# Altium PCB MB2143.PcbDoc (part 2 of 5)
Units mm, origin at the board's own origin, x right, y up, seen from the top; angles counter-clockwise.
Board outline 70 x 70 mm, 4 copper layers (Top Layer, Signal Layer 1, Signal Layer 2, Bottom Layer), stack 1.56 mm thick; 272 components, 188 nets, 1083 pads, 1158 vias.
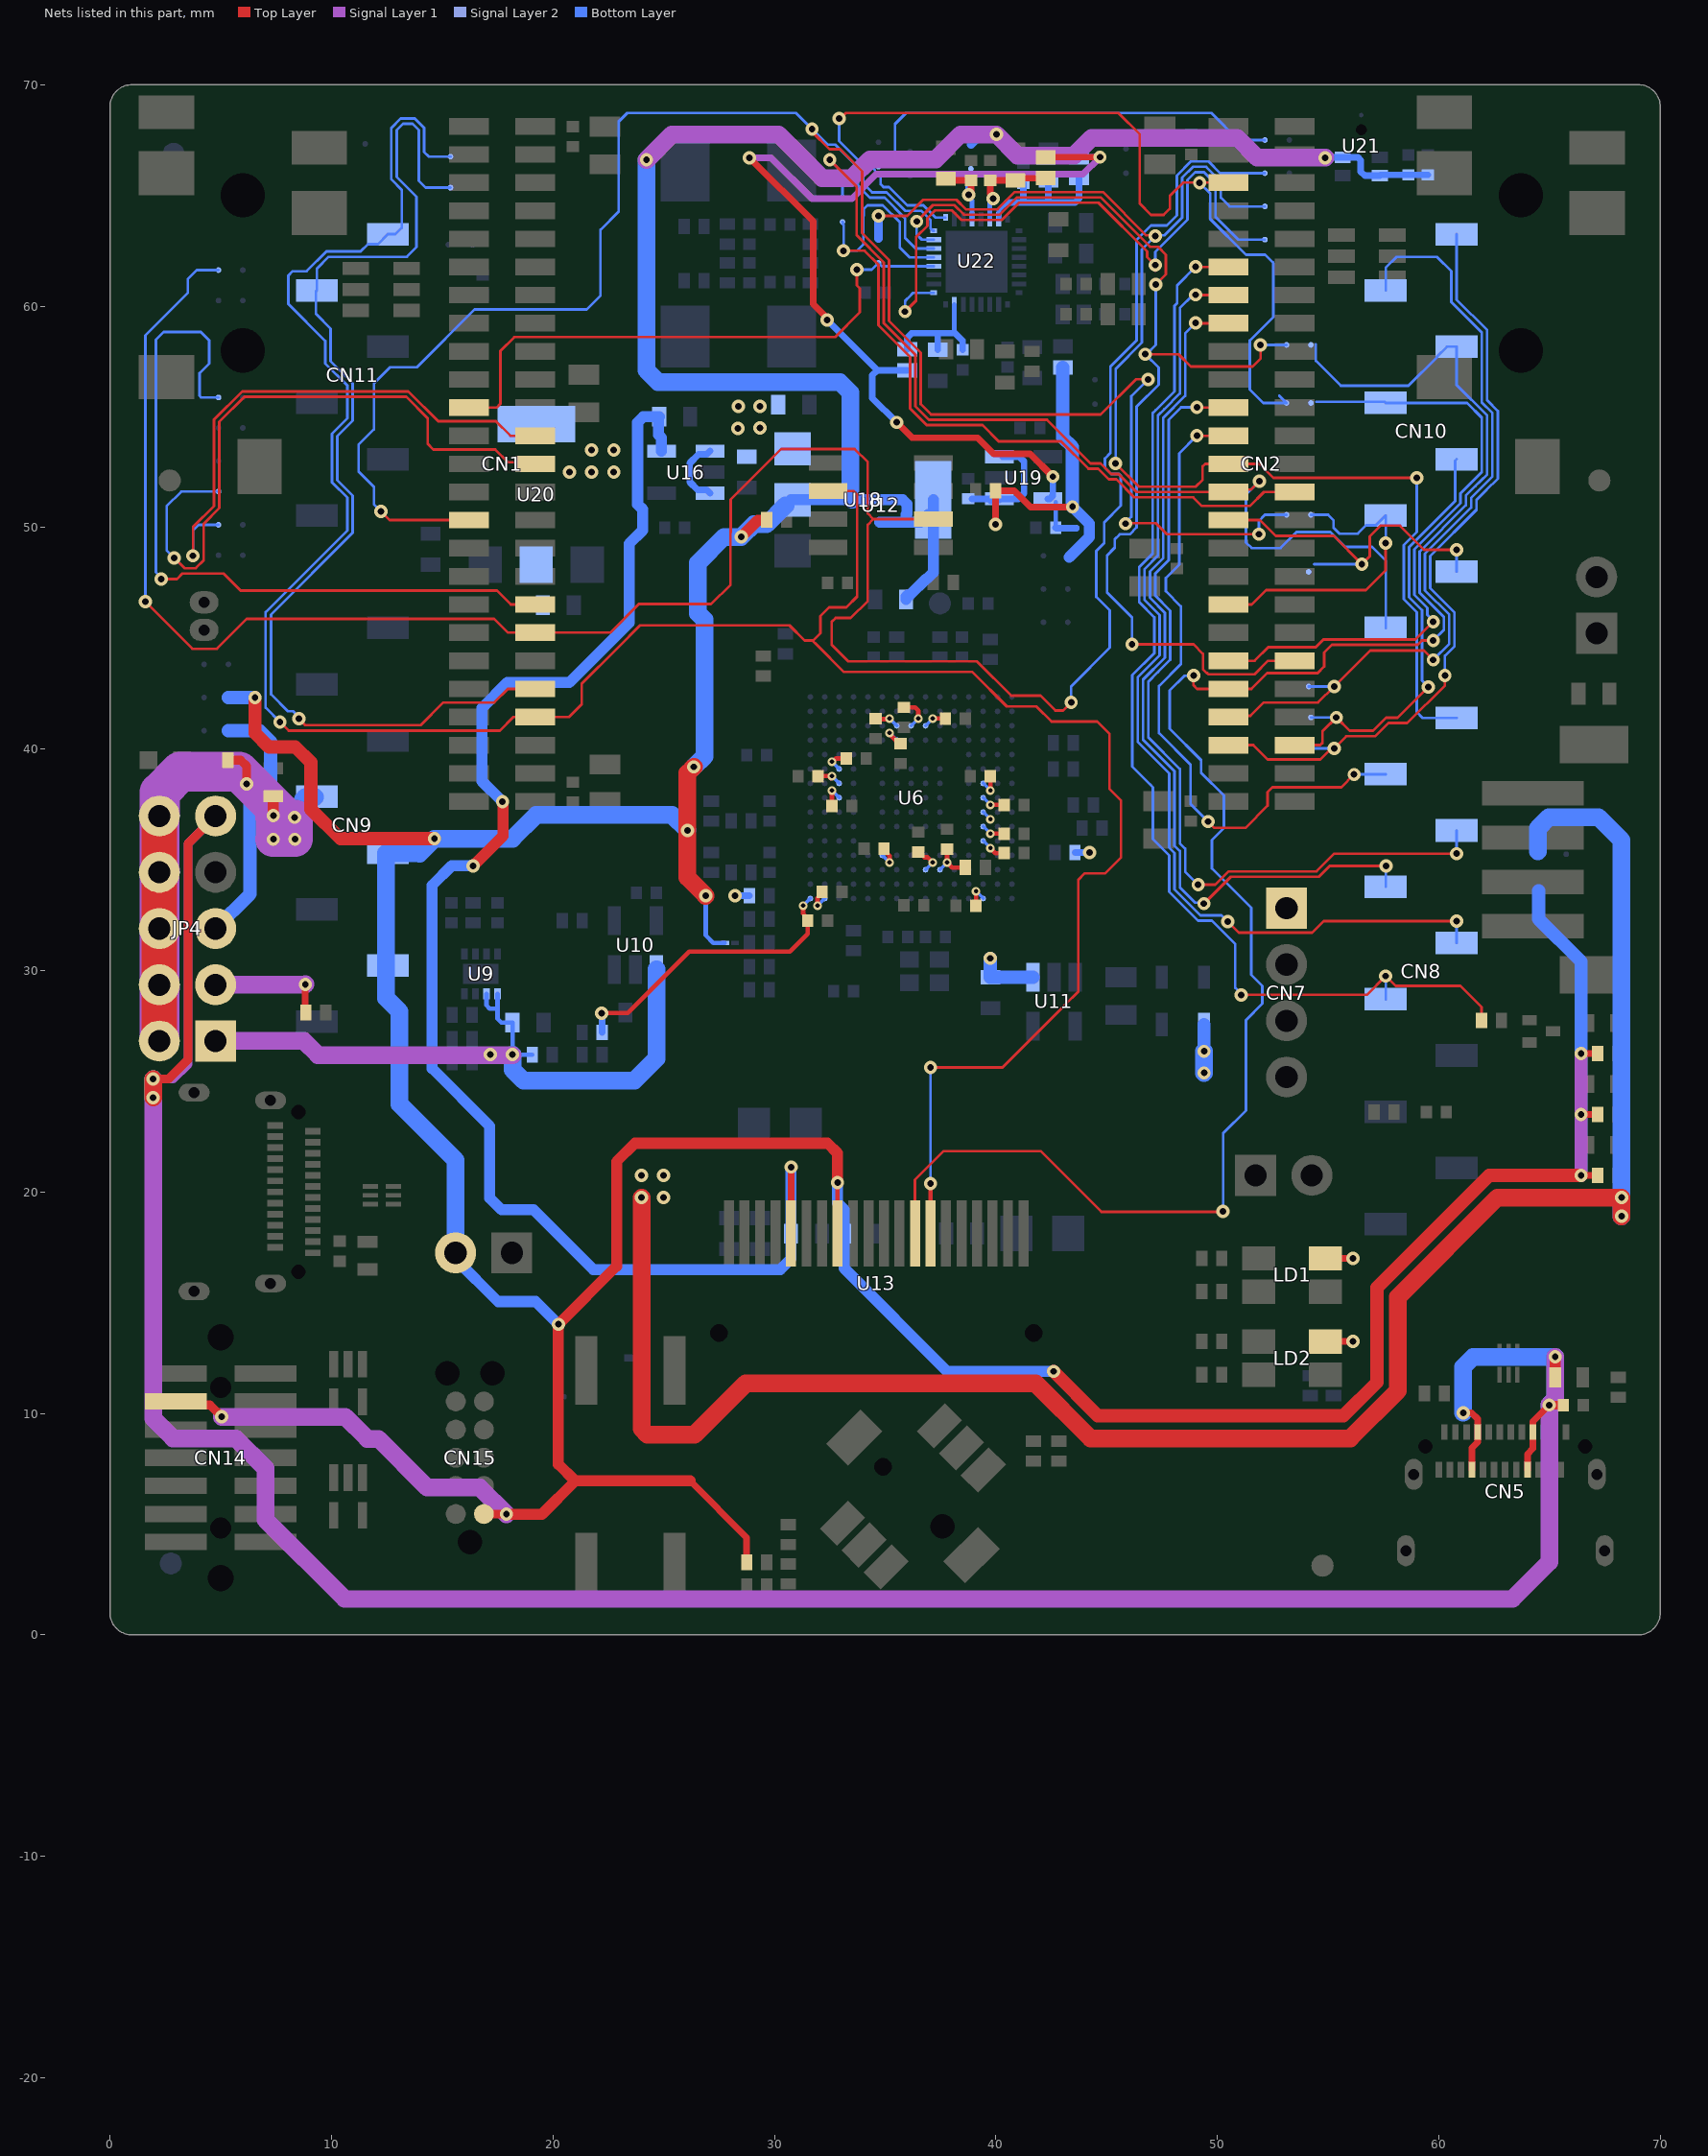
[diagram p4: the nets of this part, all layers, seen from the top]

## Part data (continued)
JP2 JP3: library part MCD-00045, "Header, 2x1, 2,54mm, VR, TH, Height 5.84mm/2.54mm", Manufacturer=SAMTEC, Manufacturer_Part_Number=TSW-102-07-x-S
JP4: library part MCD-01203, "Header, 5x2, 2.54mm, VR, TH, T=5.84mm/2.54mm", Manufacturer=SAMTEC, Manufacturer_Part_Number=TSW-105-07-G-D
L1 L3 L5 L6 L7 L8: library part MCD-02381, "Ferrite bead, 10R @100MHz, 5R, 0.75A, 0.07R, 0402, T=0.22mm", Manufacturer=MURATA, Manufacturer_Part_Number=BLM02AX100SN1D, Package=0402
LD1 LD2: library part MCD-02631, "LED Bicolor, Green/Red, 2V, 20mA,  4-PLCC", Manufacturer="WURTH ELEKTRONIK", Manufacturer_Part_Number=150141SV73110, Package=4-PLCC
LD3: library part MCD-00584, "LED Blue, 0603 SMD, 3.3 V Forward Voltage", Manufacturer=VISHAY, Manufacturer_Part_Number=VLMB1300-GS08, Package="LED 0603"
LD4: library part MCD-02901, "LED, Green, 2V, 20mA, 0603", Manufacturer=EVERLIGHT, Manufacturer_Part_Number=19-217/G7C-AN1P2/6T, Package=0603
LD5: library part MCD-00587, "LED Red, 0603 SMD, 2V Forward Voltage", Manufacturer=VISHAY, Manufacturer_Part_Number=VLMS1300-GS08, Package="LED 0603"
LD6: library part MCD-00589, "LED Green, 0603 SMD, Fw Voltage = 2.8V - 3.6V", Manufacturer=VISHAY, Manufacturer_Part_Number=VLMTG1300-GS08, Package="LED 0603"
LNK1: library part MCD-02777, "Track link on PCB 200um width for layout routing. No component assembly and no component in BOM", Manufacturer=STM, Package=LNK200
Q1: library part MCD-00280, "Buffer transistor", Manufacturer=ROHM
R1: library part MCD-00333, "Resistor, 5K1, 0402, +/-1%, 1/16W", Alternate_Manufacturer=N/A, Manufacturer=YAGEO, Manufacturer_Part_Number=RC0402FR-075K1L, Package=0402
R2: library part MCD-00409, "Resistor, 1K8, 0402, +/-1%, 1/16W", Alternate_Manufacturer=N/A, Manufacturer=YAGEO, Manufacturer_Part_Number=RC0402FR-071K8L, Package=0402
R3: library part MCD-00527, "Resistor, 820R, 0402, +/-1%, 1/16W", Alternate_Manufacturer=N/A, Manufacturer=YAGEO, Manufacturer_Part_Number=RC0402FR-07820RL, Package=0402
R4: library part MCD-00064, "Resistor, 510R, 0402, +/-1%, 1/16W", Alternate_Manufacturer=N/A, Manufacturer=YAGEO, Manufacturer_Part_Number=RC0402FR-07510RL, Package=0402
R5: library part MCD-00220, "Resistor,10K,0603,1%,1/10W", Manufacturer=YAGEO, Manufacturer_Part_Number=RC0603FR-0710KL, Package=R0603
R6 R7 R11 R15 R22: library part MCD-00333, "Resistor, 5K1, 0402, +/-1%, 1/16W", Manufacturer=YAGEO, Manufacturer_Part_Number=RC0402FR-075K1L, Package=0402
R8 R9: library part MCD-00065, "Resistor,4K7,0402,1%,1/16W", Alternate_Manufacturer=YAGEO, Alternate_Manufacturer_Part_Number=RT0402FRE074K7L, Manufacturer_Part_Number=RC0402FR-074K7L, Package=R0402
R10 R55: library part MCD-00053, "Resistor,10K,0402,1%,1/16W", Manufacturer=YAGEO, Manufacturer_Part_Number=RC0402FR-0710KL, Package=R0402
R12 R47: library part MCD-00067, "Resistor, 100R, 0402, +/- 1%, 1/16W", Manufacturer=YAGEO, Manufacturer_Part_Number=RC0402FR-07100RL, Package=0402
R13 R14 R34 R39 R40 R59: library part MCD-00059, "Resistor, 100K, 0402, +/-1%, 1/16W", Manufacturer=YAGEO, Manufacturer_Part_Number=RC0402FR-07100KL, Package=0402
R16 R18 R19 R21 R57: library part MCD-00455, "Resistor, 33R, 0402, +/-1%, 1/16W", Manufacturer=YAGEO, Manufacturer_Part_Number=RC0402FR-0733RL, Package=0402
R17 R20 R24 R58: library part MCD-00052, "Resistor, 0R, 0402, +/-5%, 1/16W", Manufacturer=YAGEO, Manufacturer_Part_Number=RC0402JR-070RL, Package=0402
R23 R26 R27 R28 R64: library part MCD-00053, "Resistor, 10K, 0402, +/-1%, 1/16W", Manufacturer=YAGEO, Manufacturer_Part_Number=RC0402FR-0710KL, Package=0402
R25 R29: library part MCD-00185, "Resistor, 3K, 0402, +/-1%, 1/16W", Manufacturer=YAGEO, Manufacturer_Part_Number=RC0402FR-073KL, Package=0402
R30 R33: library part MCD-02455, "Resistor, 3K9, 0402, +/-1%, 1/16W, +/-100ppm/°C", Manufacturer=YAGEO, Manufacturer_Part_Number=RC0402FR-073K9L, Package=0402
R31: library part MCD-00409, "Resistor, 1K8, 0402, +/-1%, 1/16W", Manufacturer=YAGEO, Manufacturer_Part_Number=RC0402FR-071K8L, Package=0402
R32: library part MCD-00381, "Resistor, 1K3, 0402, +/-1%, 1/16W", Manufacturer=YAGEO, Manufacturer_Part_Number=RC0402FR-071K3L, Package=0402
R35 R37: library part MCD-02665, "Resistor, 1K, 0402, +/-0.1%, 1/16W, +/-25ppm/°C", Manufacturer=YAGEO, Manufacturer_Part_Number=RT0402BRD071KL, Package=0402
R36 R38: library part MCD-00062, "Resistor, 330R, 0402, +/-1%, 1/16W", Manufacturer=YAGEO, Manufacturer_Part_Number=RC0402FR-07330RL, Package=0402
R41: library part MCD-00064, "Resistor,510R,0402,1%,1/16W", Manufacturer=YAGEO, Manufacturer_Part_Number=RC0402FR-07510RL, Package=R0402
R42 R44: library part MCD-00052, "Resistor,0R,0402,5%,1/16W", Manufacturer=YAGEO, Manufacturer_Part_Number=RC0402JR-070RL, Package=R0402
R43: library part MCD-00061, "Resistor,1K,0402,1%,1/16W", Manufacturer=YAGEO, Manufacturer_Part_Number=RC0402FR-071KL, Package=R0402
R45 R51 R52 R53: library part MCD-00491, "Resistor, 5K6, 0402, +/-1%, 1/16W", Manufacturer=YAGEO, Manufacturer_Part_Number=RC0402FR-075K6L, Package=0402
R46: library part MCD-00506, "Resistor,620K,0603,1%,1/10W", Manufacturer=YAGEO, Manufacturer_Part_Number=RC0603FR-07620KL, Package=R0603
R48: library part MCD-00499, "Resistor,620R,0402,1%,1/16W", Manufacturer=YAGEO, Manufacturer_Part_Number=RC0402FR-07620RL, Package=R0402
R49 R50: library part MCD-00345, "Resistor, 20R, 0603, +/-1%, 1/10W", Manufacturer=YAGEO, Manufacturer_Part_Number=RC0603FR-0720RL, Package=0603
R54: library part MCD-00057, "Resistor,2K2,0402,1%,1/16W", Manufacturer=YAGEO, Manufacturer_Part_Number=RC0402FR-072K2L, Package=R0402
R56: library part MCD-00419, "Resistor, 2K, 0402, +/-1%, 1/16W", Alternate_Manufacturer=N/A, Manufacturer=YAGEO, Manufacturer_Part_Number=RC0402FR-072KL, Package=0402
R60 R63: library part MCD-00053, "Resistor, 10K, 0402, +/-1%, 1/16W", Alternate_Manufacturer=N/A, Manufacturer=YAGEO, Manufacturer_Part_Number=RC0402FR-0710KL, Package=0402
R61 R62: library part MCD-00507, "Resistor, 680R, 0402, +/-1%, 1/16W", Manufacturer=YAGEO, Manufacturer_Part_Number=RC0402FR-07680RL, Package=0402
SB1 SB2 SB3 SB4 SB5 SB6 SB7 SB8 SB9 SB10 SB11 SB12 SB13 SB14 SB15 SB16 SB17 SB18 SB19 SB20 SB21 SB22 SB23 SB24 SB25 SB26 SB27 SB28 SB29 SB30 SB31 SB32 SB33 SB34 SB35 SB36 SB37 SB38 SB39 SB40 SB41 SB42: library part MCD-00071, "Solder Bridge ON"
STICKER-BOARD-1: library part MCD-02190, "Sticker board 25x5 mm", Manufacturer=N/A
STICKER-PRODUCT-1: library part MCD-02707, "PCB 2L2S of NUCLEO64 for MiniBoard", Manufacturer=EMS, Manufacturer_Part_Number=MB1801, Package=PCB
TP1: library part MCD-00074, "Test Point 1mm", Manufacturer=N/A
TP2: library part MCD-00630, "Test Point 0.3mm"
U1 U5: library part MCD-00247, "Quad Bidir ESD protection", Manufacturer=STMICROELECTRONICS, Manufacturer_HQ_COO=EU
U2 U7: library part MCD-01207, "High power Transient voltage suppressor:25V/35A EOS and ESD transients protection.", Manufacturer=STMICROELECTRONICS, Manufacturer_HQ_COO=EU, Manufacturer_Part_Number=ESDA25P35-1U1M, Package=QFN1610
U3: library part MCD-00170, "ESD protection 6V1", Manufacturer=STMICROELECTRONICS, Manufacturer_Part_Number=ESDALC6V1-1U2
U4 U8: library part MCD-03060, "IC, ESD protection and Common Filter High Speed serial Interfaces, 10.7 GHz", Manufacturer=STMICROELECTRONICS, Package=uQFN-6
U6: library part MCD-03851, "MCU, ARM Cortex-M7 32-bit, 512KB Flash, 276KB RAM, With Crypto", Manufacturer=STMICROELECTRONICS, Manufacturer_Part_Number=STM32F723IEK6, Package=BGA-176
U9: library part MCD-02532, "IC, eFuse with Fast Overvoltage Protection 2.7V to 18V 4A 34mOhm 8-Pin WSON", Manufacturer="TEXAS INSTRUMENTS", Package=WSON8
U10: library part MCD-00159, "500mA, Enhanced single channel power switches with active high enable pin", Alternate_Manufacturer="TEXAS INSTRUMENTS", Alternate_Manufacturer_Part_Number=TPS2051C, Manufacturer=STMICROELECTRONICS
U11: library part MCD-02514, "LDO, 3.3V, 300mA, High input voltage: 2.5V to 28V, SOT23-5L", Manufacturer=STMICROELECTRONICS, Package=SOT23-5L
U12: library part MCD-03804, "Memory, EEPROM, 1.6V to 3.6V, 32Mbit, 80MHz, SO8N, SPI interface", Manufacturer=STMICROELECTRONICS, Manufacturer_Part_Number=M95P32-IXMNT/E
U13: library part MCD-01925, "128*64 Dots 20-pin OLED display", Manufacturer=RITDISPLAY, Manufacturer_Part_Number=9OL9935718000, Package=SMT
U14 U15: library part MCD-00136, "Dual Transil array for ESD protection", Manufacturer=STMICROELECTRONICS, Manufacturer_HQ_COO=EU
U16: library part MCD-01030, "LDO VOLTAGE REGULATOR, 3.6V, 150mA, 5-SOT-23, FULL REEL", Manufacturer="TEXAS INSTRUMENTS", Package=REG_SOT23-5L
U17: library part MCD-01026, "High power transient voltage suppressor", Manufacturer=STMICROELECTRONICS, Manufacturer_Part_Number=ESDA7P120-1U1M, Package=QFN1610
U18: library part MCD-00089, "LOW DROP FIXED AND ADJUSTABLE POSITIVE VOLTAGE REGULATORS (3.3 Volts)", Manufacturer=STMICROELECTRONICS
U19: library part MCD-00078, "Ultra low drop-low noise BiCMOS voltage, regulators low ESR capacitors compatible", Manufacturer=STMICROELECTRONICS
U20: library part MCD-00088, "IC REG LDO 5V 0.8A SOT223", Manufacturer=STMICROELECTRONICS
U21: library part MCD-02122, "MEMS sensors , omnidirectionnal digital microphone", Alternate_Manufacturer=N/A, Manufacturer=STMICROELECTRONICS, Manufacturer_Part_Number=MP23DB01HPTR, Package="RHLGA 5"
U22: library part MCD-03825, "Audio Codec, Ultra Low-Power Codec for Portable Audio Applications", Manufacturer="CIRRUS LOGIC"
X1: library part MCD-01036, "Crystal, 24MHz, 6pF, +/-20ppm, 80R, 2x1.6mm", Manufacturer=NDK, Manufacturer_Part_Number=NX2016SA-24MHZ-EXS00A-CS10820, Package=2x1.6mm

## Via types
v1: diameter 0.6, hole 0.3, Top Layer to Bottom Layer, 1107 vias
v2: diameter 0.4, hole 0.2, Top Layer to Bottom Layer, tented both sides, 50 vias
v3: diameter 0.6, hole 0.3, Top Layer to Bottom Layer, tented both sides, 1 vias

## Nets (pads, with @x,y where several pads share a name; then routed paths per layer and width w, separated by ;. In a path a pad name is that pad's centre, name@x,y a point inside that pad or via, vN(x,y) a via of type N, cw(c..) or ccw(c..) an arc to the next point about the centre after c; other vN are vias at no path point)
1V8: C86.2 L5.1 L7.1 L8.1 TP2.1 U19.5 | length 48.3
  Top Layer w0.3: v1(28.875,66.7) 31.75,63.825 31.75,60.081 32.375,59.456 v1(32.375,59.375) ; v1(35.525,54.75) 36.22,54.055 39.16,54.055 39.89,53.325 41.55,53.325 v1(42.575,52.3) ; L8.1@42.25,66.725 v1(44.7,66.725)
  Signal Layer 1 w0.3: v1(28.875,66.7) 29.85,66.7 31.7,64.85 33.5,64.85 34.6,65.95 43.925,65.95 v1(44.7,66.725)
  Bottom Layer w0.2: C86.2@42.7,50 U19.5@42.7,51.15
  Bottom Layer w0.3: v1(32.375,59.375) 34.65,57.1 ; v1(35.525,54.75) 34.425,55.85 34.425,56.875 34.65,57.1 ; L5.1@36,57.1 34.65,57.1 ; U19.5@42.35,51.3 42.425,51.3 42.575,51.45 v1@42.575,52.291 ; C86.2@42.7,50 42.725,49.975 TP2.1@43.625,49.975 ; L7.1@43.75,66.725 v1(44.7,66.725)
3V3: C33.2 C34.1 C74.1 C80.2 C85.2 CN9.2 CN9.4 CN14.3 CN15.1 JP2.2 L6.1 LNK1.1 R41.1 R56.1 R60.2 R61.1 R62.1 R63.1 SB14.1 SB18.1 SB34.2 SB36.2 U13.8 U18.2 U18.4 U19.1 U19.3 U21.2 U21.5 | length 308.9
  Top Layer w0.2: U13.8@32.85,18.125 v1(32.85,20.425)
  Top Layer w0.3: 26.2,6.95 28.75,4.4 R56.1@28.75,3.275 ; v1(39.988,50.138) R60.2@39.988,51.665 40.835,51.665 41.575,50.925 43.45,50.925 v1(43.463,50.938) ; v1(66.425,20.75) R62.1@67.175,20.75 ; v1(66.425,23.5) R61.1@67.175,23.5 ; v1(66.425,26.25) R41.1@67.175,26.25
  Top Layer w0.4: CN14.3@2.968,10.54 3.121,10.387 4.513,10.387 v1(5.05,9.85) ; CN15.1@16.885,5.46 16.895,5.45 v1(17.9,5.45)
  Top Layer w0.5: v1(17.9,5.45) 19.506,5.45 21.006,6.95 26.2,6.95 ; 20.97,6.985 20.25,7.706 v1(20.25,14.025) 22.875,16.65 22.875,21.375 23.7,22.2 32.4,22.2 32.85,21.75 v1(32.85,20.425) ; v1(28.5,49.575) 29.248,50.323 29.621,50.323 R63.1@29.65,50.353
  Top Layer w0.6: v1(6.55,42.325) 6.55,40.725 7.175,40.1 8.368,40.1 9.075,39.393 9.075,37.281 10.406,35.95 v1(14.65,35.95) ; v1(42.6,11.9) 44.6,9.9 55.7,9.9 57.2,11.4 57.2,15.675 62.275,20.75 v1(66.425,20.75)
  Top Layer w0.8: v1(26.365,39.195) 26.075,38.904 v1(26.075,36.325) 26.075,34.2 v1(26.9,33.375)
  Signal Layer 1 w0.6: v1(66.425,20.75) v1(66.425,23.5) v1(66.425,26.25)
  Signal Layer 1 w0.8: v1(5.05,9.85) 10.625,9.85 11.625,8.85 12.125,8.85 14.325,6.65 16.7,6.65 v1(17.9,5.45) ; v1(24.225,66.6) 25.375,67.75 30.19,67.75 32.16,65.78 33.482,65.78 34.322,66.62 37.28,66.62 38.41,67.75 v1(40.025,67.75) 40.975,66.8 43.525,66.8 44.325,67.6 50.9,67.6 51.8,66.7 v1(54.875,66.7)
  Bottom Layer w0.2: v1(26.9,33.375) 26.9,31.594 27.244,31.25 LNK1.1@27.75,31.25
  Bottom Layer w0.3: C85.2@38.93,51.3 39.673,51.3 U19.1@39.774,51.199 ; U19.1@39.783,51.2 U19.1@39.988,51.226 ; v1(39.988,50.138) U19.1@39.988,51.226 ; U19.1@40.15,51.3 41.025,51.3 41.275,51.55 41.275,52.975 41.05,53.2 U19.3@40.3,53.2 ; U19.1@40.157,51.248 U19.1@39.988,51.226 ; v1(54.875,66.7) 54.883,66.708 U21.2@55.662,66.708 56.352,66.708 56.475,66.585 56.475,66.075 56.664,65.886 U21.5@57.338,65.886 57.377,65.925 C34.1@58.625,65.925 C33.2@59.5,65.925
  Bottom Layer w0.4: SB18.1@38.875,67.3 39.225,67.65 39.846,67.65 39.946,67.75 v1(40.025,67.75)
  Bottom Layer w0.5: JP2.2@15.605,17.25 15.605,16.968 17.523,15.05 19.225,15.05 v1(20.25,14.025) ; U18.2@30.25,50.75 30.75,51.25 U18.2@30.825,51.25 33.525,51.25 35.798,51.25 35.98,51.068 35.98,50.617 35.95,50.587 35.95,50.237 ; v1(32.85,20.425) 32.85,19.5 33.15,19.2 C74.1@33.15,18.125 33.15,16.55 37.8,11.9 v1(42.6,11.9) ; 34.762,50.237 35.95,50.237 ; C80.2@35.95,46.75 35.95,46.875 36.02,46.945 36.112,46.945 36.852,47.685 36.885,47.685 37.175,47.975 U18.4@37.175,51.25 ; U18.4@36.95,50.587 36.6,50.237 35.95,50.237 ; SB36.2@43.313,48.663 44.22,49.57 44.22,50.18 v1(43.463,50.938)
  Bottom Layer w0.6: SB14.1@5.35,42.325 v1(6.55,42.325) ; L6.1@43.025,57.225 43.025,54.069 43.45,53.644 43.45,50.95 v1(43.463,50.938) ; 64.5,33.6 64.5,32.325 66.425,30.4 v1(66.425,26.25) v1(66.425,23.5) v1(66.425,20.75)
  Bottom Layer w0.8: JP2.2@15.605,17.25 15.605,21.435 13.075,23.965 13.075,28.15 12.472,28.754 12.472,35.286 13.964,35.286 13.975,35.275 v1(14.65,35.95) 18.175,35.95 19.25,37.025 25.375,37.025 v1(26.075,36.325) ; v1(24.225,66.6) 24.225,57.1 24.75,56.575 32.95,56.575 33.425,56.1 33.425,51.35 33.525,51.25 ; v1(26.365,39.195) 26.845,39.674 26.845,45.835 26.55,46.13 26.55,48.4 27.725,49.575 v1(28.5,49.575) 29.075,50.15 29.65,50.15 U18.2@30.5,51
3V3_STLK: C50.1 C51.1 C52.1 C53.1 C54.1 C55.1 C56.1 C57.1 C58.1 C60.2 C61.1 C62.1 C63.1 C64.1 C65.1 C66.1 C67.1 C68.1 CN7.1 LD1.4 LD2.4 R28.2 R39.1 R64.2 U6.C1 U6.C5 U6.C6 U6.C7 U6.C8 U6.C9 U6.F3 U6.G3 U6.G13 U6.H13 U6.J12 U6.J13 U6.K4 U6.N8 U6.N9 U6.N10 U6.P1 U6.R1 U11.1 | length 39
  Top Layer w0.2: v1(22.2,28.075) 23.375,28.075 26.15,30.85 30.7,30.85 31.5,31.65 31.5,32.375 31.3,32.575 v2(31.3,32.925) ; v2@31.95,32.975 31.95,33.275 32.15,33.475 C66.1@32.15,33.5 ; C52.1@31.975,38.775 32.45,38.775 v2@32.55,38.675 ; C50.1@32.6,37.425 v2(32.6,38.125) ; v2(32.6,39.425) 32.636,39.425 32.786,39.575 C53.1@33.225,39.575 ; C54.1@34.75,41.35 35.175,41.35 v2(35.2,41.375) ; C65.1@34.95,35.45 34.95,35.425 35.105,35.27 35.106,35.27 35.2,35.176 v2(35.2,34.875) ; v2@35.225,40.725 35.225,40.65 35.47,40.405 35.47,40.38 35.625,40.225 C51.1@35.65,40.225 ; C55.1@35.85,41.875 36.35,41.875 36.5,41.725 v2@36.5,41.4 ; C64.1@36.5,35.35 36.525,35.35 36.764,35.111 36.914,35.111 v2(37.15,34.875) ; v2@37.15,41.35 37.175,41.375 C56.1@37.725,41.375 ; C63.1@37.8,35.475 v2(37.8,34.875) 38.025,34.65 R64.2@38.625,34.65 ; v2@39.075,33.525 39.1,33.5 C68.1@39.1,32.925 ; v2@39.7,36.15 39.725,36.175 C61.1@40.375,36.175 ; v2(39.75,35.525) 39.975,35.3 C62.1@40.375,35.3 ; v2@39.75,37.45 39.775,37.475 C58.1@40.375,37.475 ; C57.1@39.75,38.775 39.75,38.175 v2@39.775,38.15 ; C62.1@40.3,35.275 C62.1@40.375,35.2
  Top Layer w0.3: LD2.4@54.875,13.25 v1(56.125,13.25) ; LD1.4@54.875,17 v1(56.125,17)
  Bottom Layer w0.15: v2(31.3,32.925) U6.R1@31.625,33.25 ; v2(31.95,32.925) U6.P1@32.275,33.25 ; v2(32.6,38.125) U6.N8@32.925,37.8 ; v2(32.6,38.775) U6.N9@32.925,38.45 ; v2(32.6,39.425) U6.N10@32.925,39.1 ; U6.K4@34.875,35.2 v2(35.2,34.875) ; v2(35.2,40.725) U6.J12@35.525,40.4 ; v2(35.2,41.375) U6.J13@35.525,41.05 ; U6.H13@36.175,41.05 v2(36.5,41.375) ; U6.G3@36.825,34.55 v2(37.15,34.875) ; U6.G13@36.825,41.05 v2(37.15,41.375) ; U6.F3@37.475,34.55 v2(37.8,34.875) ; v2(39.1,33.575) U6.C1@39.425,33.25 ; U6.C5@39.425,35.85 v2(39.75,35.525) ; U6.C6@39.425,36.5 v2(39.75,36.175) ; U6.C7@39.425,37.15 v2(39.75,36.825) ; U6.C8@39.425,37.8 v2(39.75,37.475) ; U6.C9@39.425,38.45 v2(39.75,38.125)
  Bottom Layer w0.3: v1(22.2,28.075) 22.225,28.05 R39.1@22.225,27.2 ; R28.2@43.575,35.325 v1(44.23,35.325)
  Bottom Layer w0.6: C60.2@39.75,29.695 v1(39.75,30.55) ; C60.2@39.775,29.725 39.805,29.695 U11.1@41.675,29.695
3V6: C75.1 C77.1 U13.5 U16.5 | length 68.1
  Top Layer w0.3: U13.5@30.75,18.125 v1(30.75,21.125)
  Top Layer w0.5: v1(16.4,34.725) 17.75,36.075 17.75,37.6 v1(17.725,37.625)
  Bottom Layer w0.5: v1(16.4,34.725) 15.425,34.725 14.55,33.85 14.55,25.575 17.15,22.975 17.15,19.725 17.675,19.2 19.125,19.2 21.825,16.5 30.268,16.5 30.75,16.982 C75.1@30.75,18.125 v1(30.75,21.125) ; v1@17.706,37.644 16.8,38.55 16.8,41.85 17.95,43 20.748,43 23.45,45.702 23.45,49.275 24.05,49.875 24.05,50.823 23.825,51.048 23.825,54.75 24.075,55 C77.1@24.8,55 24.775,54.975 24.775,54.175 24.9,54.05 U16.5@24.9,53.45
5V: C78.1 C81.2 CN9.5 JP4.2 JP4.4 JP4.6 JP4.8 JP4.10 R22.2 R48.2 SB33.2 U16.1 U16.3 U17.1 U18.3 | length 128.2
  Top Layer w0.4: R48.2@5.325,39.5 5.9,39.5 6.175,39.225 v1(6.175,38.425)
  Top Layer w0.5: v1(7.375,37) U17.1@7.375,37.875
  Top Layer w0.8: v1(24,19.75) 24,9.31 24.269,9.041 26.393,9.041 28.707,11.355 41.795,11.355 44.275,8.875 56,8.875 58.15,11.025 58.15,15.25 62.65,19.75 v1(68.25,19.75) v1(68.25,18.9)
  Top Layer w1.6: JP4.2@2.23,26.815 JP4.4@2.23,29.355 JP4.6@2.23,31.895 JP4.8@2.23,34.435 JP4.10@2.23,36.975
  Signal Layer 1 w1.6: JP4.10@2.23,36.975 2.24,36.985 JP4.10@2.272,37.017 ; v1@7.359,35.925 v1(7.375,35.925) ; v1@7.359,36.916 v1@7.375,36.916 ; v1(7.375,35.925) v1(8.35,35.925) 8.35,36.916 v1(8.332,36.916) v1@7.375,36.916 ; v1(7.375,35.925) v1@7.375,36.916
  Signal Layer 1 w1.8: JP4.2@2.23,26.815 2.23,29.24 2.24,29.25 JP4.4@2.25,29.25 ; JP4.4@2.23,29.355 JP4.6@2.23,31.895 JP4.6@2.23,31.98 ; JP4.10@2.23,36.975 JP4.8@2.23,34.48 ; JP4.10@2.24,36.985 2.24,37.02 2.25,37.03 2.25,38.05 3.175,38.975 5.838,38.975 7.85,36.963 ; JP4.6@2.25,32 JP4.6@2.23,31.98 ; JP4.8@2.25,34.5 JP4.8@2.23,34.48 ; JP4.6@2.23,31.98 JP4.8@2.23,34.435 JP4.8@2.23,34.48
  Bottom Layer w0.3: U16.3@27.1,51.55 26.95,51.7 26.536,51.7 26.175,52.061 26.175,52.907 26.568,53.3 26.95,53.3 U16.1@27.1,53.45 ; v1(28.22,33.375) R22.2@28.875,33.375
  Bottom Layer w0.8: v1(7.375,37) 7.813,37 7.888,36.925 v1@8.325,36.925 ; v1(8.332,36.916) 8.332,36.932 8.714,37.314 8.714,37.716 8.824,37.826 CN9.5@9.267,37.826 ; 64.475,35.375 64.475,36.425 64.975,36.925 67.2,36.925 68.25,35.875 v1(68.25,18.9)
  other v1: 25,19.75 24,20.75 25,20.75 28.35,54.475 29.35,54.5 28.375,55.475 29.35,55.475
5V_EXT: JP4.5 SB15.1 | length 11.6
  Bottom Layer w0.6: JP4.5@4.77,31.895 6.325,33.45 6.325,37.425 7.25,38.35 7.25,40.325 6.75,40.825 SB15.1@5.35,40.825
5V_STLK: C43.2 C47.2 JP4.1 R29.1 U9.5 U9.6 U10.1 | length 30.7
  Signal Layer 1 w0.8: JP4.1@4.77,26.815 8.76,26.815 9.394,26.181 17.272,26.181 v1@18.175,26.181
  Bottom Layer w0.2: U9.6@17,28.95 17,28.425 17.15,28.275 17.5,28.275 ; U9.5@17.5,28.95 17.5,28.275 ; v1(18.175,26.2) C43.2@18.175,27.645 ; C43.2@18.175,27.65 17.675,27.65 17.5,27.825 17.5,28.275 ; v1@18.28,26.195 R29.1@19.075,26.195
  Bottom Layer w0.8: v1(18.175,26.2) 18.175,25.525 18.675,25.025 23.675,25.025 24.675,26.025 C47.2@24.675,28.1 U10.1@24.675,30.05
  other v1: 17.175,26.2
5V_USB_MCU: C14.2 CN5.A4 CN5.A9 CN5.B4 CN5.B9 JP4.9 U2.1 | length 139.5
  Top Layer w0.25: v1(64.988,10.38) v1@64.993,10.375 ; U2.1@65.237,11.613 U2.1@65.25,11.625 ; v1@65.25,12.55 v1(65.255,12.555)
  Top Layer w0.3: v1(61.1,10.025) 61.48,10.025 61.75,9.755 CN5.A4@61.75,9.16 61.75,8.872 61.75,8.7 61.5,8.45 CN5.B9@61.5,7.46 ; CN5.B4@64,7.46 64,8.163 64.25,8.413 CN5.A9@64.25,9.16 64.25,9.448 64.25,9.632 v1@64.993,10.375
  Top Layer w0.4: v1(1.95,25.1) 2.65,25.1 3.525,25.975 3.525,35.73 JP4.9@4.77,36.975 ; v1@64.993,10.375 C14.2@65.613,10.375
  Top Layer w0.5: U2.1@65.25,11.625 v1@65.25,12.55
  Top Layer w0.8: v1@1.95,24.275 v1(1.95,25.1)
  Signal Layer 1 w0.4: v1(1.95,25.1) 2.85,25.1 3.525,25.775 3.525,35.73 JP4.9@4.77,36.975
  Signal Layer 1 w0.8: v1(1.95,25.1) v1(1.95,24.25) 1.95,9.775 2.85,8.875 5.675,8.875 7.025,7.525 7.025,5.2 10.605,1.62 11.66,1.62 60.74,1.62 63.32,1.62 64.988,3.288 v1(64.988,10.38) 65.255,10.648 v1(65.255,12.555)
  Signal Layer 2 w0.8: v1@1.95,24.275 v1(1.95,25.1)
  Bottom Layer w0.8: v1(1.95,24.25) v1(1.95,25.1) ; v1(61.1,10.025) 61.1,12.1 61.555,12.555 v1(65.255,12.555) ; v1(64.988,10.38) 65.258,10.65 v1@65.258,12.552
5V_VIN: C84.2 D2.1 JP4.3 R43.2 U20.2 U20.4 | length 7.5
  Top Layer w0.3: R43.2@8.817,28.1 v1@8.817,29.367
  Signal Layer 1 w0.8: JP4.3@4.77,29.355 8.805,29.355 v1(8.825,29.375)
  Bottom Layer w0.6: v1(49.4,26.35) D2.1@49.4,27.555
  Bottom Layer w0.8: v1(49.4,25.375) v1(49.4,26.35)
  other v1: 20.75,52.5 21.75,52.5 22.75,52.5 21.75,53.5 22.75,53.5
ARD.D0_RX: CN2.45 CN10.1 SB42.1 | length 35.6
  Top Layer w0.12: CN2.45@50.5,40.175 51.625,40.175 52.275,39.525 54.65,39.525 55.15,40.025 v1(55.275,40.025) 55.825,40.575 57.125,40.575 57.723,41.173 58.576,41.173 60.275,42.871 v1(60.275,43.325)
  Bottom Layer w0.12: SB42.1@54.125,40.025 v1(55.275,40.025) ; v1(60.275,43.325) 60.275,44.211 60.71,44.646 60.71,46.162 59.615,47.257 59.615,48.718 61.701,50.804 61.701,51.244 62.128,51.672 62.153,51.697 62.661,52.204 62.661,55.264 62.181,55.744 62.181,58.911 60.808,60.284 CN10.1@60.808,63.247
ARD.D1_TX: CN2.43 CN10.2 SB41.1 | length 36.6
  Top Layer w0.12: CN2.43@50.5,41.445 50.55,41.495 51.495,41.495 52.1,42.1 54.55,42.1 v1(55.275,42.825) 56.9,44.45 59.325,44.45 v1(59.75,44.025)
  Bottom Layer w0.12: SB41.1@54.125,42.825 v1(55.275,42.825) ; CN10.2@57.603,60.707 57.603,61.725 58.098,62.22 59.923,62.22 60.568,61.575 60.568,60.184 61.941,58.812 61.941,55.645 62.421,55.165 62.421,52.304 62.054,51.937 61.888,51.771 61.461,51.344 61.461,50.903 59.375,48.817 59.375,47.158 60.47,46.063 60.47,44.745 v1(59.75,44.025)
ARD.D2_IO: CN2.41 CN10.3 SB26.2 U13.13 | length 82.5
  Top Layer w0.12: U13.13@36.35,18.125 36.35,20.55 37.645,21.845 42.019,21.845 44.764,19.1 50.23,19.1 v1(50.26,19.13) ; v1(48.925,43.325) 48.925,42.875 49.085,42.715 CN2.41@50.5,42.715 51.54,42.715 52.255,43.43 54.53,43.43 54.825,43.725 54.825,44.354 55.176,44.705 59.041,44.705 59.236,44.9 v1(59.75,44.9)
  Bottom Layer w0.12: v1(48.925,43.325) 48.911,43.311 48.515,43.311 47.845,42.64 47.845,40.92 49.27,39.495 49.27,38.924 50.295,37.899 50.295,36.427 49.76,35.892 49.76,34.605 51.53,32.835 51.53,29.803 52.035,29.298 52.035,28.502 51.29,27.757 51.29,23.672 50.26,22.642 v1(50.26,19.13) ; 54.45,58.275 54.45,57.525 55.575,56.4 58.625,56.4 59.916,57.691 59.916,57.717 60.366,58.167 CN10.3@60.808,58.167 60.808,56.438 62.181,55.065 62.181,52.425 62.181,52.403 61.884,52.106 61.648,51.87 61.221,51.443 61.221,51.002 59.135,48.916 59.135,47.059 60.23,45.964 60.23,45.38 v1(59.75,44.9)
ARD.D3_TIM: CN2.39 CN10.4 SB24.2 | length 28.6
  Top Layer w0.12: CN2.39@50.5,43.985 51.685,43.985 52.3,44.6 54.446,44.6 54.791,44.945 58.942,44.945 v1(59.75,45.753)
  Bottom Layer w0.12: 54.475,55.675 57.556,55.675 CN10.4@57.603,55.627 61.28,55.627 61.941,54.966 61.941,52.524 61.941,52.502 60.981,51.542 60.981,51.102 58.895,49.016 58.895,46.959 59.48,46.374 59.48,46.063 59.75,45.793 v1(59.75,45.753)
ARD.D4_INT: CN2.46 CN10.5 SB35.2 | length 20.6
  Top Layer w0.12: CN2.46@53.5,40.175 54.65,40.175 54.75,40.275 54.75,40.8 v1(55.375,41.425) 55.975,40.825 57.036,40.825 57.623,41.413 58.138,41.413 v1(59.525,42.8)
  Bottom Layer w0.12: SB35.2@54.225,41.425 v1(55.375,41.425) ; v1(59.525,42.8) 59.525,42.809 59.24,43.094 59.24,46.275 58.655,46.86 58.655,49.115 60.732,51.193 60.732,53.011 CN10.5@60.808,53.087
ARD.D5_TIM: CN2.35 CN10.6 SB22.2 | length 14.5
  Top Layer w0.12: CN2.35@50.5,46.525 51.55,46.525 52.2,47.175 56.714,47.175 57.6,48.061 v1(57.6,49.3)
  Bottom Layer w0.12: SB22.2@54.225,50.575 55.005,50.575 55.005,50.57 55.25,50.325 55.25,49.983 55.508,49.725 56.339,49.725 56.711,50.097 57.153,50.097 CN10.6@57.603,50.547 57.603,49.304 v1(57.6,49.3)
ARD.D6_TIM: CN2.29 CN10.7 SB2.1 | length 16
  Top Layer w0.12: CN2.29@50.5,50.335 51.919,50.335 52.634,49.62 55.255,49.62 v1(56.525,48.35) 56.88,48.705 56.88,49.598 57.367,50.085 58.249,50.085 59.334,49 v1(60.8,49)
  Bottom Layer w0.12: 54.375,48.35 v1(56.525,48.35) ; CN10.7@60.8,48.016 CN10.7@60.808,48.007 60.808,48.992 v1(60.8,49)
ARD.D7_IO: CN2.27 CN10.8 SB9.2 | length 45.3
  Top Layer w0.12: v1(32.5,66.6) 33.718,65.382 33.718,63.196 34.94,61.974 34.94,59.231 36.368,57.803 36.368,55.474 36.977,54.865 42.31,54.865 44.28,52.895 44.726,52.895 45.201,52.42 45.541,52.42 46.356,51.605 CN2.27@50.5,51.605 50.605,51.71 51.51,51.71 v1(51.9,52.1)
  Bottom Layer w0.12: v1(32.5,66.6) 33.075,66.025 SB9.2@33.075,64.9 ; v1(51.9,52.1) 51.295,51.495 51.295,49.325 51.545,49.075 52.861,49.075 53.581,49.795 55.098,49.795 55.766,49.128 56.987,49.128 57.603,48.511 CN10.8@57.603,45.467
ARD.D8_IO: CN2.25 CN8.1 SB3.2 SB8.2 | length 62.7
  Top Layer w0.12: v1(34.7,64.075) 35.996,64.075 36.721,64.8 38.22,64.8 38.65,64.37 40.074,64.37 40.854,65.15 44.833,65.15 46.792,63.191 47.169,63.191 v1(47.2,63.16) ; v1(45.4,52.9) 46.455,51.845 49.02,51.845 49.337,52.162 49.337,52.763 49.45,52.875 CN2.25@50.5,52.875 51.91,52.875 52.535,52.25 v1(59,52.25)
  Bottom Layer w0.12: v1(45.4,52.9) 45.415,52.915 45.415,57.176 46.59,58.351 46.59,62.55 v1(47.2,63.16) 47.234,63.194 47.605,63.194 48.41,63.999 48.41,65.798 48.902,66.29 49.498,66.29 50.16,65.628 50.16,64.89 50.55,64.5 SB3.2@52.15,64.5 ; v1(59,52.25) 59,49.8 58.415,49.215 58.415,46.76 59,46.175 59,41.675 59.272,41.403 CN8.1@60.808,41.403
  Bottom Layer w0.4: SB8.2@34.7,63.05 v1(34.7,64.075)
ARD.D9_TIM: CN2.23 CN8.2 | length 30.5
  Top Layer w0.12: v1(49.075,54.15) 49.08,54.145 CN2.23@50.5,54.145 ; v1(49.575,36.725) 49.584,36.725 49.869,36.44 51.265,36.44 52.267,37.442 52.267,38.058 52.485,38.275 55.6,38.275 v1(56.175,38.85)
  Bottom Layer w0.12: v1(49.075,54.15) 48.28,53.355 48.28,48.33 47.675,47.725 47.675,47.125 48.355,46.445 48.355,43.829 47.365,42.839 47.365,40.721 48.79,39.296 48.79,37.51 v1(49.575,36.725) ; v1(56.175,38.85) 56.188,38.863 CN8.2@57.603,38.863
ARD.D10_TIM_SPI2_NSS: CN2.21 CN8.3 | length 39.1
  Top Layer w0.12: v1(49.075,55.425) 49.085,55.415 CN2.21@50.5,55.415 ; v1(49.135,33.872) 49.909,33.872 50.512,34.475 54.486,34.475 55.286,35.275 v1(60.8,35.275)
  Bottom Layer w0.12: v1(49.075,55.425) 48.361,55.425 47.8,54.864 47.8,48.529 47.195,47.924 47.195,46.926 47.875,46.246 47.875,44.028 47.336,43.489 47.311,43.464 46.885,43.038 46.885,40.523 48.31,39.098 48.31,35.737 48.55,35.497 48.55,34.457 v1(49.135,33.872) ; v1(60.8,35.275) 60.808,35.284 CN8.3@60.808,36.323
ARD.D11_TIM_SPI2_MOSI: CN2.15 CN8.4 | length 40.5
  Top Layer w0.12: v1(49.025,59.24) 49.04,59.225 CN2.15@50.5,59.225 ; v1(49.396,33.019) 50.612,34.235 54.585,34.235 55.075,34.725 v1(57.625,34.725)
  Bottom Layer w0.12: v1(49.025,59.24) 48.55,58.765 48.55,55.953 47.56,54.963 47.56,48.628 46.955,48.023 46.955,46.827 47.635,46.147 47.635,44.127 46.645,43.137 46.645,40.423 48.07,38.998 48.07,35.638 48.31,35.398 48.31,33.754 49.001,33.063 49.351,33.063 v1(49.396,33.019) ; CN8.4@57.603,33.783 57.603,34.704 v1(57.625,34.725)
ARD.D12_SPI2_MISO: CN2.13 CN8.5 | length 45.5
  Top Layer w0.12: v1(49.025,60.51) 49.04,60.495 CN2.13@50.5,60.495 ; v1(50.475,32.2) 50.971,31.705 54.28,31.705 54.8,32.225 v1(60.8,32.225)
  Bottom Layer w0.12: v1(49.025,60.51) 48.91,60.51 48.31,59.91 48.31,56.052 47.604,55.347 47.32,55.062 47.32,48.728 46.715,48.123 46.715,46.727 47.395,46.047 47.395,44.227 46.405,43.237 46.405,40.324 47.83,38.899 47.83,35.538 48.07,35.298 48.07,33.655 49.235,32.49 50.186,32.49 v1@50.475,32.2 ; v1(60.8,32.225) 60.808,32.217 CN8.5@60.808,31.243
ARD.D13_SPI2_SCK: CN2.11 CN8.6 R42.1 | length 51.9
  Top Layer w0.12: v1(49.025,61.78) 49.04,61.765 CN2.11@50.5,61.765 ; v1(51.075,28.9) 56.75,28.9 v1(57.6,29.75) 58.05,29.3 60.975,29.3 61.925,28.35 R42.1@61.925,27.75
  Bottom Layer w0.12: v1(49.025,61.78) 48.185,60.94 48.185,60.124 48.07,60.01 48.07,56.152 47.214,55.296 47.08,55.162 47.08,48.827 46.475,48.222 46.475,46.628 47.155,45.948 47.155,44.326 46.165,43.336 46.165,39.2 46.977,38.389 46.982,38.389 47.095,38.276 47.095,35.934 47.83,35.199 47.83,33.556 49.136,32.25 49.747,32.25 50.81,31.187 50.81,29.21 51.075,28.945 v1(51.075,28.9) ; v1(57.6,29.75) 57.603,29.747 CN8.6@57.603,28.703
ARD_ADC.A0: CN1.24 SB10.2 | length 24.8
  Top Layer w0.12: v1(3.75,48.725) 3.75,50.025 4.7,50.975 4.7,54.875 5.975,56.15 13.475,56.15 14.825,54.8 17.425,54.8 18.08,54.145 CN1.24@19.21,54.145
  Bottom Layer w0.12: v1(3.75,48.725) 3.75,49.875 4,50.125 SB10.2@4.9,50.125
ARD_ADC.A1: CN1.26 SB21.2 | length 30
  Top Layer w0.12: v1(2.906,48.623) 3.364,48.165 3.869,48.165 4.23,48.526 4.23,50.166 4.94,50.876 4.94,54.776 6.074,55.91 13.376,55.91 14.35,54.936 14.35,53.775 14.6,53.525 17.4,53.525 17.975,52.95 19.135,52.95 CN1.26@19.21,52.875
  Bottom Layer w0.12: v1(2.906,48.623) 2.56,48.969 2.56,50.96 3.225,51.625 SB21.2@4.9,51.625
ARD_ADC.A2: CN1.36 SB25.2 | length 34.7
  Top Layer w0.12: v1(2.32,47.675) 3.025,47.675 3.275,47.925 5.125,47.925 5.9,47.15 17.475,47.15 18.1,46.525 CN1.36@19.21,46.525
  Bottom Layer w0.12: v1(2.32,47.675) 2.32,47.745 2.08,47.985 2.08,56.6 2.08,58.48 2.425,58.825 4.1,58.825 4.475,58.45 4.475,57.4 4.05,56.975 4.05,55.945 4.12,55.875 SB25.2@4.9,55.875
ARD_ADC.A3: CN1.38 SB4.2 SB30.2 U12.2 | length 113.6
  Top Layer w0.12: v1(1.6,46.65) 3.725,44.525 4.825,44.525 6.175,45.875 17.35,45.875 17.97,45.255 CN1.38@19.21,45.255 22.591,45.255 23.879,46.543 27.143,46.543 28.02,47.42 28.02,48.597 28.02,49.774 28.025,49.779 28.025,51.275 30.3,53.55 33.625,53.55 34.215,52.96 34.215,50.635 34.47,50.38 ; U12.2@37.175,50.38 34.47,50.38 ; v1(43.4,42.1) 43.04,41.74 42.686,41.74 42.021,42.405 40.692,42.405 39.137,43.96 33.337,43.96 32.59,44.707 32.59,45.74 32.765,45.915 33.444,45.915 34.215,46.686 34.215,50.125 34.47,50.38
  Bottom Layer w0.12: v1(1.6,46.65) 1.6,57.575 1.6,58.679 3.512,60.591 3.512,61.213 3.925,61.625 SB30.2@4.9,61.625 ; v1(43.4,42.1) 43.4,42.832 45.145,44.577 45.145,46.261 44.54,46.866 44.54,48.942 44.89,49.292 44.89,50.233 45.64,50.983 45.64,52.35 45.57,52.42 45.201,52.42 44.92,52.701 44.92,53.12 45.175,53.375 45.175,57.275 46.35,58.45 46.35,62.989 47.001,63.64 47.711,63.64 48.17,64.099 48.17,65.898 48.802,66.53 49.598,66.53 50.128,66 SB4.2@52.15,66
ARD_ADC.A4: CN1.42 CN11.5 SB27.1 | length 50.9
  Top Layer w0.12: v1(8.525,41.375) 8.825,41.075 14.025,41.075 15.05,42.1 17.35,42.1 17.965,42.715 CN1.42@19.21,42.715
  Bottom Layer w0.12: v1(8.525,41.375) 8.525,41.456 8.276,41.705 8.034,41.705 7.27,42.469 7.27,46.077 10.957,49.764 10.957,51.449 10.265,52.141 10.265,54.134 10.957,54.826 10.957,56.514 9.965,57.506 9.965,58.985 9.3,59.65 9.3,60.662 CN11.5@9.345,60.707 9.345,61.695 9.875,62.225 13.4,62.225 13.835,62.66 13.835,64.94 12.945,65.83 12.945,67.949 13.231,68.235 13.665,68.235 13.95,67.95 13.95,65.65 14.25,65.35 SB27.1@15.375,65.35
ARD_ADC.A5: CN1.44 CN11.6 SB29.1 U12.6 U13.14 | length 118.8
  Top Layer w0.12: v1(7.675,41.225) 8.07,40.83 17.605,40.83 18.22,41.445 CN1.44@19.21,41.445 20.72,41.445 21.3,42.025 21.3,42.946 22.914,44.561 23.937,45.583 30.681,45.583 31.364,44.9 31.718,44.9 ; U12.6@32.425,51.65 33.58,51.65 33.735,51.495 33.735,46.885 33.245,46.395 32.47,46.395 32.075,46 32.075,45.221 31.754,44.9 31.718,44.9 ; v1(37.05,25.627) 40.302,25.627 42.82,28.145 42.824,28.145 43.105,28.426 43.105,28.43 43.72,29.045 43.72,34.099 44.001,34.38 44.926,34.38 45.655,35.109 45.655,37.674 45.135,38.194 45.135,40.673 44.573,41.235 42.512,41.235 41.822,41.925 40.493,41.925 38.938,43.48 33.138,43.48 31.914,44.704 31.718,44.9
  Top Layer w0.2: U13.14@37.05,18.125 v1(37.05,20.375)
  Bottom Layer w0.12: v1(7.675,41.225) 7.03,41.87 7.03,46.176 10.717,49.863 10.717,51.349 10.025,52.041 10.025,54.234 10.717,54.926 10.717,56.415 9.725,57.407 9.725,58.425 8.05,60.1 8.05,61.375 8.25,61.575 8.886,61.575 9.776,62.465 11.315,62.465 11.647,62.797 12.1,62.797 CN11.6@12.55,63.247 12.889,63.247 13.175,63.533 13.175,65.255 12.705,65.725 12.705,68.048 13.132,68.475 13.764,68.475 14.19,68.049 14.19,66.96 14.4,66.75 SB29.1@15.375,66.75 ; v1(37.05,20.375) v1(37.05,25.627)
Audio.FS_A: CN1.29 SB22.1 U22.30 | length 89.6
  Top Layer w0.12: v1(12.236,50.733) 12.634,50.335 CN1.29@16.21,50.335 ; v1(31.7,68) 31.7,67.875 32.495,67.08 32.962,67.08 33.958,66.084 33.958,63.296 35.18,62.074 35.18,59.331 36.608,57.902 36.608,55.574 37.077,55.105 44.735,55.105 46.325,56.695 46.861,56.695 v1(46.87,56.686) ; v1(45.85,50.175) 45.875,50.2 47.225,50.2 47.725,49.7 v1(51.875,49.7)
  Bottom Layer w0.12: v1(12.236,50.733) 11.917,51.052 11.917,51.846 11.225,52.538 11.225,53.737 11.917,54.429 11.917,56.503 12.651,57.237 13.855,57.237 16.468,59.85 21.525,59.85 22.15,60.475 22.15,63.446 22.97,64.266 22.97,68.331 23.359,68.72 25.399,68.72 30.98,68.72 v1(31.7,68) 32.412,67.288 32.748,67.288 33.78,66.256 33.78,65.426 34.312,64.894 34.973,64.894 35.902,63.964 35.902,63.077 36.379,62.6 U22.30@37.2,62.6 ; v1(45.85,50.175) 45.85,50.214 46.12,50.484 46.12,55.936 v1(46.87,56.686) ; v1(51.875,49.7) 51.875,50.3 52.15,50.575 SB22.1@53.125,50.575
Audio.MCLK_A: CN1.21 SB8.1 U22.28 | length 26.5
  Top Layer w0.12: CN1.21@16.21,55.415 17.45,55.415 17.625,55.59 17.625,57.975 18.25,58.6 32.74,58.6 33.855,59.715 33.855,60.799 33.725,60.929 v1(33.725,61.65)
  Bottom Layer w0.12: v1(33.725,61.65) 34.4,61.65 SB8.1@34.7,61.95 34.85,61.8 U22.28@37.2,61.8
Audio.SCK_A: CN2.28 SB9.1 U22.29 | length 37.2
  Top Layer w0.12: v1(33.125,62.5) 34.075,62.5 34.7,61.875 34.7,59.132 36.128,57.704 36.128,55.375 36.878,54.625 39.396,54.625 40.126,53.895 42.941,53.895 44.181,52.655 44.375,52.655 44.627,52.655 45.102,52.18 45.441,52.18 46.256,51.365 48.91,51.365 49.3,50.975 51.475,50.975 52.105,51.605 CN2.28@53.5,51.605
  Bottom Layer w0.12: SB9.1@33.075,63.8 33.101,63.774 33.101,63.687 33.125,63.663 v1(33.125,62.5) 33.725,62.5 34.02,62.795 34.02,64.074 34.025,64.079 34.025,64.375 34.205,64.555 34.899,64.555 35.662,63.792 35.662,62.638 36.101,62.2 U22.29@37.2,62.2
Audio.SD_A: CN2.5 SB24.1 U22.32 | length 44.1
  Top Layer w0.12: v1(32.925,68.475) 32.99,68.475 33.235,68.72 34.199,68.72 42.601,68.72 45.53,68.72 46.5,67.75 46.5,64.625 47.005,64.12 47.574,64.12 47.855,64.401 47.855,64.97 48.46,65.575 CN2.5@50.5,65.575
  Bottom Layer w0.12: v1(32.925,68.475) 32.925,67.45 34.02,66.355 34.02,65.525 34.412,65.134 35.072,65.134 35.901,64.305 36.624,64.305 37.053,63.876 37.053,63.507 37.16,63.4 U22.32@37.2,63.4 ; v1(49.2,65.57) 49.68,65.09 49.68,63.931 51.291,62.32 52.164,62.32 52.505,61.979 52.505,61.97 52.525,61.95 52.525,59.504 51.47,58.449 51.47,56.23 52.075,55.625 SB24.1@53.125,55.625 52.8,55.95
Audio.SD_B: CN2.40 SB26.1 U22.31 | length 50.5
  Top Layer w0.12: v1(36.425,63.825) 37.16,64.56 38.121,64.56 38.551,64.13 40.173,64.13 40.953,64.91 44.733,64.91 46.963,62.68 47.32,62.68 47.68,62.32 47.68,61.43 v1(47.225,60.975) ; v1(46.15,44.725) 48.925,44.725 49.35,44.3 49.35,43.605 49.525,43.43 49.545,43.43 49.6,43.375 51.675,43.375 52.285,43.985 CN2.40@53.5,43.985 ; v1(46.75,57.825) 48.25,57.825 48.8,57.275 51.6,57.275 51.95,57.625 v1(51.95,58.25)
  Bottom Layer w0.12: v1(36.425,63.825) 36.425,63.233 36.658,63 U22.31@37.2,63 ; v1(46.15,44.725) 46.15,45.935 45.02,47.065 45.02,48.744 45.37,49.094 45.37,49.475 45.59,49.695 46.049,49.695 46.36,50.006 46.36,55.46 47.35,56.45 47.35,56.885 47.35,57.225 v1(46.75,57.825) 46.8,57.825 47.225,58.25 v1(47.225,60.975) ; v1(51.95,58.25) SB26.1@53.125,58.25
AVDD: C20.2 C31.2 L5.2 U22.23 | length 5.8
  Bottom Layer w0.2: U22.23@38.125,60.075 38.125,58.825 38.175,58.775
  Bottom Layer w0.3: L5.2@36,58.05 36,58.575 36.2,58.775 37.425,58.775 ; C31.2@37.375,58.025 37.375,58.725 37.425,58.775 ; C20.2@38.5,58.025 38.5,58.45 38.175,58.775 37.425,58.775
CPVDD: C91.2 C92.2 L7.2 U22.7 | length 8.1
  Bottom Layer w0.2: U22.7@40.125,63.925 40.135,63.935 40.135,64.31 40.5,64.675 ; 43.725,64.825 43.725,65.75 L7.2@43.75,65.775
  Bottom Layer w0.3: 40.5,64.675 41.35,64.675 ; C92.2@41.25,65.55 41.25,64.775 41.35,64.675 ; C91.2@42.375,65.675 42.375,64.725 42.325,64.675 ; L7.2@43.75,65.775 43.75,64.85 43.725,64.825 43.575,64.675 42.325,64.675 ; 41.35,64.675 42.325,64.675
DBVDD: C89.2 C90.2 SB18.2 U22.4 | length 3.9
  Top Layer w0.3: C89.2@37.75,65.75 37.825,65.675 C90.2@38.875,65.675 38.875,65.206 38.775,65.106 v1(38.775,65.025)
  Bottom Layer w0.2: v1(38.775,65.025) 38.775,64.917 38.925,64.767 U22.4@38.925,63.925
  Bottom Layer w0.3: v1(38.775,65.025) 38.775,65.775 38.875,65.875
DCVDD: C93.2 C94.2 L8.2 U22.6 | length 4.4
  Top Layer w0.3: v1(39.875,64.85) 39.875,64.931 39.75,65.056 C94.2@39.75,65.675 C93.2@40.875,65.675 40.975,65.775 L8.2@42.25,65.775
  Bottom Layer w0.2: U22.6@39.725,63.925 39.725,64.825 v1@39.75,64.85
DMIC_CK1: SB11.2 SB32.1 U22.1 | length 24.7
  Bottom Layer w0.12: 34.541,66.134 34.375,66.3 SB32.1@34.7,66.3 35.37,66.3 35.445,66.375 35.445,68.22 35.945,68.72 39.472,68.72 45.199,68.72 49.73,68.72 50.95,67.5 SB11.2@52.15,67.5 ; 34.8,66.05 34.8,65.5 34.926,65.374 35.172,65.374 36,64.545 36.723,64.545 37.268,64.001 37.435,64.001 U22.1@37.725,64
DMIC_D1: SB12.2 U22.25 | length 29.6
  Top Layer w0.12: v1(35.9,59.75) 36.4,60.25 36.4,63.121 36.905,63.626 36.905,63.966 37.259,64.32 38.021,64.32 38.451,63.89 40.273,63.89 41.053,64.67 44.634,64.67 46.835,62.469 46.835,62.217 v1(47.2,61.852) v1@47.2,61.6
  Bottom Layer w0.12: v1(35.9,59.75) 35.9,60.229 36.01,60.34 36.06,60.39 36.271,60.6 U22.25@37.2,60.6 ; v1@47.2,61.6 v1(47.2,61.852) 47.2,62.45 48.65,63.9 48.65,65.699 49.001,66.05 49.399,66.05 49.92,65.529 49.92,64.03 50.95,63 SB12.2@52.15,63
